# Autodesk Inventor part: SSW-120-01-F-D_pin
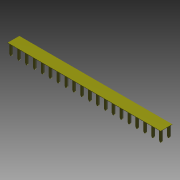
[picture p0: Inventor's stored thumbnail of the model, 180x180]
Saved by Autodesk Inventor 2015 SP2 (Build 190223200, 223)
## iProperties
Category: PARTsolutions
Company: SAMTEC
Created: 2015-08
Part Number: SSW-120-01-F-D_pin
Catalog Web Link: www.cadenas.de
Description: SSW Series Pin-SSW Series - (2,54 mm) .100" Surface Mount Terminal & Through-Hole .025" Square Post Socket
Vendor: SAMTEC
Document SubType Name: Modeling
Designer: PARTuser1
Manufacturer: SAMTEC
Mass: 0.0669125 g
Surface Area: 7.06347 cm^2
Volume: 0.0669125 cm^3
Density: 1 g/cm^3
Material: Allgemein
Appearance: PSOLRGB-255-255-0
PSOL_IDENT_0: {$CADENAS_DATA\23d-libs\samtec\modelling\ssw\parts\ssw_pin.prj},220 {VTYP=3D},{NB=SSW-120-01-F-D_pin
PSOL_IDENT_1: },{LINA=SSW-120-01-F-D_pin},{NN=SSW Series Pin},{DATE=19.06.2015 09:33:41},{GEOMDATE=19.06.2015 09:3
PSOL_IDENT_2: 3:00},{VERSION=},{LINEID=10},{LINESUBID=-1},{WBVAR=POS,LS,PLOPT,ROW,TOPT,POLOPT,LLOPT}  {NB=SSW-120-
PSOL_IDENT_3: 01-F-D_pin},{LINA=SSW-120-01-F-D_pin},{KT=DUMMY},{PN=SSW-120-01-F-D},{SERIES=SSW},{POS=20},{POSATOF=
PSOL_IDENT_4: 20},{LS=01},{LSALG= '01','-01','02','-02','03','-03','04','-04','06','-06','21','-21','22','-22','23'
PSOL_IDENT_5: ,'-23','24','-24' },{PLOPT=F},{PLOPTALG= 'G','-G - Gold, 20micro\" Au / 50micro\" Ni Min on Contact,
PSOL_IDENT_6: 3micro\" Au / 50micro\" Ni Min on Tail','S','-S - Selective, 30micro\" Au / 50micro\" Ni Min on Con
PSOL_IDENT_7: tact, Matte Tin Tail','H','-H - Heavy Gold 30micro\" Au / 50micro\" Ni Min on Contact, 3micro\" Au /
PSOL_IDENT_8: 50micro\" Ni Min on Tail' ,'F','-F - Flash Selective, 3micro\" Au / 50micro\" Ni Min on Contact, Ma
PSOL_IDENT_9: tte Tin Tail','STL','-STL - Selective, 30micro\" Au / 50micro\" Ni Min on Contact Area, Tin/Lead (90
PSOL_IDENT_10: /10 +/-5%) Tail','SM','-SM - Selective, 30micro\" Au / 50micro\" Ni Min on Contact, Matte Tin Tail','
PSOL_IDENT_11: FM','-FM - Flash Selective, 3micro\" Au / 50micro\" Ni Min on Contact, Matte Tin Tail','L','-L - Lig
PSOL_IDENT_12: ht Selective, 10micro\" Au / 50micro\" Ni Min on Contact Area, Matte Tin Tail','T','-T - Matte Tin C
PSOL_IDENT_13: ontact and Tail','E','-E - 50micro\" Extra Heavy Gold in Contact Area, 3micro\" Gold on Tail','TL','
PSOL_IDENT_14: -TL - Tin/Lead (90/10 ± 5%) Contact and Tail','TM','-TM - Matte Tin Contact and Tail' },{ROW=D},{ROW
PSOL_IDENT_15: ALG= 'S','-S - Single','D','-D - Double','T','-T - Triple', 'P','-P - Single Notched','Q','-Q - Trip
PSOL_IDENT_16: le with only Outer 2 Rows Filled' },{TOPT=},{TOPTALG= '','Straight' },{TOPTPN=},{POLOPT=},{POLOPTALG=
PSOL_IDENT_17: '','Not Selected','001','001','002','002','003','003','004','004','005','005','006','006','007','00
PSOL_IDENT_18: 7','008','008','009','009','010','010','011','011','012','012','013','013','014','014','015','015','
PSOL_IDENT_19: 016','016','017','017','018','018','019','019','020','020','021','021','022','022','023','023','024'
PSOL_IDENT_20: ,'024','025','025','026','026','027','027','028','028','029','029','030','030','031','031','032','03
PSOL_IDENT_21: 2','033','033','034','034','035','035','036','036','037','037','038','038','039','039','040','040' }
PSOL_IDENT_22: ,{POLOPTMAX=480},{POLOPTMAX2='001','001','002','002','003','003','004','004','005','005','006','006'
PSOL_IDENT_23: ,'007','007','008','008','009','009','010','010','011','011','012','012','013','013','014','014','01
PSOL_IDENT_24: 5','015','016','016','017','017','018','018','019','019','020','020','021','021','022','022','023','
PSOL_IDENT_25: 023','024','024','025','025','026','026','027','027','028','028','029','029','030','030','031','031'
PSOL_IDENT_26: ,'032','032','033','033','034','034','035','035','036','036','037','037','038','038','039','039','04
PSOL_IDENT_27: 0','040'},{POLARIZE='001','001','002','002','003','003','004','004','005','005','006','006','007','0
PSOL_IDENT_28: 07','008','008','009','009','010','010','011','011','012','012','013','013','014','014','015','015','
PSOL_IDENT_29: 016','016','017','017','018','018','019','019','020','020','021','021','022','022','023','023','024'
PSOL_IDENT_30: ,'024','025','025','026','026','027','027','028','028','029','029','030','030','031','031','032','03
PSOL_IDENT_31: 2','033','033','034','034','035','035','036','036','037','037','038','038','039','039','040','040','
PSOL_IDENT_32: 041','041','042','042','043','043','044','044','045','045','046','046','047','047','048','048','049'
PSOL_IDENT_33: ,'049','050','050','051','051','052','052','053','053','054','054','055','055','056','056','057','05
PSOL_IDENT_34: 7','058','058','059','059','060','060','061','061','062','062','063','063','064','064','065','065','
PSOL_IDENT_35: 066','066','067','067','068','068','069','069','070','070','071','071','072','072','073','073','074'
PSOL_IDENT_36: ,'074','075','075','076','076','077','077','078','078','079','079','080','080','081','081','082','08
PSOL_IDENT_37: 2','083','083','084','084','085','085','086','086','087','087','088','088','089','089','090','090','
PSOL_IDENT_38: 091','091','092','092','093','093','094','094','095','095','096','096','097','097','098','098','099'
PSOL_IDENT_39: ,'099','100','100','101','101','102','102','103','103','104','104','105','105','106','106','107','10
PSOL_IDENT_40: 7','108','108','109','109','110','110','111','111','112','112','113','113','114','114','115','115','
PSOL_IDENT_41: 116','116','117','117','118','118','119','119','120','120','121','121','122','122','123','123','124'
PSOL_IDENT_42: ,'124','125','125','126','126','127','127','128','128','129','129','130','130','131','131','132','13
PSOL_IDENT_43: 2','133','133','134','134','135','135','136','136','137','137','138','138','139','139','140','140','
PSOL_IDENT_44: 141','141','142','142','143','143','144','144','145','145','146','146','147','147','148','148','149'
PSOL_IDENT_45: ,'149','150','150'},{POLOPTPN=},{LLOPT=},{LLOPTALG= '','Not Selected','LL','-LL - Locking Lead' },{L
PSOL_IDENT_46: LOPTPN=},{B=0.104},{C=0.000},{R=2.020},{OEN=2}
NN: SSW Series Pin
NT: SSW Series - (2,54 mm) .100" Surface Mount Terminal & Through-Hole .025" Square Post Socket
NB: SSW-120-01-F-D_pin
NBSYN: $PN._pin
LINA: SSW-120-01-F-D_pin
SERIES: SSW
POS: -20
LS: -01
PLOPT: -F - Flash Selective, 3micro" Au / 50micro" Ni Min on Contact, Matte Tin Tail
ROW: -D - Double
TOPT: Straight
POLOPT: Not Selected
LLOPT: Not Selected
SUPPLIER: SAMTEC
ARTICLENO: SSW-120-01-F-D_pin
BOMINFO: SSW-120-01-F-D_pin
CREATOR: CADENAS GmbH
Title: SSW-120-01-F-D_pin
Author: Cadenas PARTsolutions
Comments: SSW Series - (2,54 mm) .100" Surface Mount Terminal & Through-Hole .025" Square Post Socket
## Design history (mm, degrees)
sketch "Sketch_2"
  geometry: L1 (3.658, 1.473)-(0, 1.473); L2 (0, 1.473)-(0, 1.067); L3 (0, 1.067)-(3.531, 1.067); L4 (3.531, 1.067)-(3.531, -1.067); L5 (3.531, -1.067)-(0, -1.067); L6 (0, -1.067)-(0, -1.473); L7 (0, -1.473)-(3.658, -1.473); L8 (3.658, -1.473)-(3.658, 1.473)
  constraints: 16 end point
extrude "Extrusion1" join sketch "Sketch_2" stored distance "d0" = 49.3014; taper "d1" = 0 deg
sketch "Sketch_13"
  geometry: L1 (-24.651, 1.88)-(-24.651, -1.88); L2 (-24.651, -1.88)-(24.651, -1.88); L3 (24.651, -1.88)-(24.651, 1.88); L4 (24.651, 1.88)-(-24.651, 1.88)
  constraints: 8 end point
extrude "Extrusion2" join sketch "Sketch_13" distance "d2" = 0.127; taper "d3" = 0 deg
sketch "Sketch_8"
  geometry: L1 (-26.276, -21.869)-(99.936, -21.869); L2 (99.936, -21.869)-(99.936, 3.531); L3 (99.936, 3.531)-(98.184, 3.531); L4 (98.184, 3.531)-(98.184, -8.89); L5 (98.184, -8.89)-(97.396, -8.89); L6 (97.396, -8.89)-(97.396, 3.531); L7 (97.396, 3.531)-(95.644, 3.531); L8 (95.644, 3.531)-(95.644, -8.89); L9 (95.644, -8.89)-(94.856, -8.89); L10 (94.856, -8.89)-(94.856, 3.531); L11 (94.856, 3.531)-(93.104, 3.531); L12 (93.104, 3.531)-(93.104, -8.89); L13 (93.104, -8.89)-(92.316, -8.89); L14 (92.316, -8.89)-(92.316, 3.531); L15 (92.316, 3.531)-(90.564, 3.531); L16 (90.564, 3.531)-(90.564, -8.89); L17 (90.564, -8.89)-(89.776, -8.89); L18 (89.776, -8.89)-(89.776, 3.531); L19 (89.776, 3.531)-(88.024, 3.531); L20 (88.024, 3.531)-(88.024, -8.89); L21 (88.024, -8.89)-(87.236, -8.89); L22 (87.236, -8.89)-(87.236, 3.531); L23 (87.236, 3.531)-(85.484, 3.531); L24 (85.484, 3.531)-(85.484, -8.89); L25 (85.484, -8.89)-(84.696, -8.89); L26 (84.696, -8.89)-(84.696, 3.531); L27 (84.696, 3.531)-(82.944, 3.531); L28 (82.944, 3.531)-(82.944, -8.89); L29 (82.944, -8.89)-(82.156, -8.89); L30 (82.156, -8.89)-(82.156, 3.531); L31 (82.156, 3.531)-(80.404, 3.531); L32 (80.404, 3.531)-(80.404, -8.89); L33 (80.404, -8.89)-(79.616, -8.89); L34 (79.616, -8.89)-(79.616, 3.531); L35 (79.616, 3.531)-(77.864, 3.531); L36 (77.864, 3.531)-(77.864, -8.89); L37 (77.864, -8.89)-(77.076, -8.89); L38 (77.076, -8.89)-(77.076, 3.531); L39 (77.076, 3.531)-(75.324, 3.531); L40 (75.324, 3.531)-(75.324, -8.89); L41 (75.324, -8.89)-(74.536, -8.89); L42 (74.536, -8.89)-(74.536, 3.531); L43 (74.536, 3.531)-(72.784, 3.531); L44 (72.784, 3.531)-(72.784, -8.89); L45 (72.784, -8.89)-(71.996, -8.89); L46 (71.996, -8.89)-(71.996, 3.531); L47 (71.996, 3.531)-(70.244, 3.531); L48 (70.244, 3.531)-(70.244, -8.89); L49 (70.244, -8.89)-(69.456, -8.89); L50 (69.456, -8.89)-(69.456, 3.531); L51 (69.456, 3.531)-(67.704, 3.531); L52 (67.704, 3.531)-(67.704, -8.89); L53 (67.704, -8.89)-(66.916, -8.89); L54 (66.916, -8.89)-(66.916, 3.531); L55 (66.916, 3.531)-(65.164, 3.531); L56 (65.164, 3.531)-(65.164, -8.89); L57 (65.164, -8.89)-(64.376, -8.89); L58 (64.376, -8.89)-(64.376, 3.531); L59 (64.376, 3.531)-(62.624, 3.531); L60 (62.624, 3.531)-(62.624, -8.89); L61 (62.624, -8.89)-(61.836, -8.89); L62 (61.836, -8.89)-(61.836, 3.531); L63 (61.836, 3.531)-(60.084, 3.531); L64 (60.084, 3.531)-(60.084, -8.89)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
  constraints: 400 end point
extrude "Extrusion3" cut sketch "Sketch_8" stored distance "d4" = 50.8; taper "d5" = 0 deg
sketch "Sketch_6"
  geometry: L1 (-24.524, 0.44)-(-24.524, -2.54); L2 (-24.524, -2.54)-(24.524, -2.54); L3 (24.524, -2.54)-(24.524, 0.44); L4 (24.524, 0.44)-(24.27, 0); L5 (24.27, 0)-(23.99, 0); L6 (23.99, 0)-(23.736, 0.44); L7 (23.736, 0.44)-(23.736, -2.032); L8 (23.736, -2.032)-(21.984, -2.032); L9 (21.984, -2.032)-(21.984, 0.44); L10 (21.984, 0.44)-(21.73, 0); L11 (21.73, 0)-(21.45, 0); L12 (21.45, 0)-(21.196, 0.44); L13 (21.196, 0.44)-(21.196, -2.032); L14 (21.196, -2.032)-(19.444, -2.032); L15 (19.444, -2.032)-(19.444, 0.44); L16 (19.444, 0.44)-(19.19, 0); L17 (19.19, 0)-(18.91, 0); L18 (18.91, 0)-(18.656, 0.44); L19 (18.656, 0.44)-(18.656, -2.032); L20 (18.656, -2.032)-(16.904, -2.032); L21 (16.904, -2.032)-(16.904, 0.44); L22 (16.904, 0.44)-(16.65, 0); L23 (16.65, 0)-(16.37, 0); L24 (16.37, 0)-(16.116, 0.44); L25 (16.116, 0.44)-(16.116, -2.032); L26 (16.116, -2.032)-(14.364, -2.032); L27 (14.364, -2.032)-(14.364, 0.44); L28 (14.364, 0.44)-(14.11, 0); L29 (14.11, 0)-(13.83, 0); L30 (13.83, 0)-(13.576, 0.44); L31 (13.576, 0.44)-(13.576, -2.032); L32 (13.576, -2.032)-(11.824, -2.032); L33 (11.824, -2.032)-(11.824, 0.44); L34 (11.824, 0.44)-(11.57, 0); L35 (11.57, 0)-(11.29, 0); L36 (11.29, 0)-(11.036, 0.44); L37 (11.036, 0.44)-(11.036, -2.032); L38 (11.036, -2.032)-(9.284, -2.032); L39 (9.284, -2.032)-(9.284, 0.44); L40 (9.284, 0.44)-(9.03, 0); L41 (9.03, 0)-(8.75, 0); L42 (8.75, 0)-(8.496, 0.44); L43 (8.496, 0.44)-(8.496, -2.032); L44 (8.496, -2.032)-(6.744, -2.032); L45 (6.744, -2.032)-(6.744, 0.44); L46 (6.744, 0.44)-(6.49, 0); L47 (6.49, 0)-(6.21, 0); L48 (6.21, 0)-(5.956, 0.44); L49 (5.956, 0.44)-(5.956, -2.032); L50 (5.956, -2.032)-(4.204, -2.032); L51 (4.204, -2.032)-(4.204, 0.44); L52 (4.204, 0.44)-(3.95, 0); L53 (3.95, 0)-(3.67, 0); L54 (3.67, 0)-(3.416, 0.44); L55 (3.416, 0.44)-(3.416, -2.032); L56 (3.416, -2.032)-(1.664, -2.032); L57 (1.664, -2.032)-(1.664, 0.44); L58 (1.664, 0.44)-(1.41, 0); L59 (1.41, 0)-(1.13, 0); L60 (1.13, 0)-(0.876, 0.44); L61 (0.876, 0.44)-(0.876, -2.032); L62 (0.876, -2.032)-(-0.876, -2.032); L63 (-0.876, -2.032)-(-0.876, 0.44); L64 (-0.876, 0.44)-(-1.13, 0)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
  constraints: 240 end point
extrude "Extrusion4" cut sketch "Sketch_6" stored distance "d6" = 25.4; taper "d7" = 0 deg
node "pin_XY"
node "pin_YZ"
node "pin_ZX"
node "pin_X"
node "pin_Y"
node "pin_Z"
node "pin_Center"
body "Solid1"
